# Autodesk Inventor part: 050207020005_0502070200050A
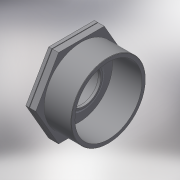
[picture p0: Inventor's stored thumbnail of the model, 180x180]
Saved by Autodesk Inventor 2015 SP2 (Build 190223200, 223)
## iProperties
Created: 2017-05
Part Number: 050207020005_0502070200050A
Material: Generic
Description: PLASSON REDUCING BUSHING 2"-1/2"
Document SubType Name: Modeling
Designer: KIM
Density: 1 g/cm^3
Appearance: Default
Author: KIM
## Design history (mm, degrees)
derived "050207.ipt"
feature "Solid1::050207.ipt"
tag "TaggingFeature1"
body "Solid1"
other parameters: "d1" = 59.614, "d2" = 63, "d5" = 25, "d8" = 0.41, "d12" = 0, "d15" = 41, "d19" = 0, "d30" = 10.25, "d31" = 5.125, "d33" = 18.631, "d34" = 53.6526, "d36" = 3.15, "d37" = 22.3572, "d38" = 30.75, "d39" = 16.7679, "d40" = 2.5, "d41" = 0, "H_" = 41, "R_" = 59.614, "E_" = 63, "l_2" = 25, "Rp_" = 18.631
